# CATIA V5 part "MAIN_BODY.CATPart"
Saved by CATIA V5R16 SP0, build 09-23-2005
Part number: MAIN_BODY
Bounding box of the stored display mesh (mm): x -7.493 to 7.493, y -7.5 to 7.5, z -13 to 86.2
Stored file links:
  D:\Format\Downloads\1_SXEDIA_EKSARTHMATON_POU_DINONTAI_ETOIMA (3) (2)\AMORTISER_parts\MAIN_BODY.CATPart
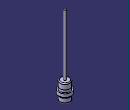
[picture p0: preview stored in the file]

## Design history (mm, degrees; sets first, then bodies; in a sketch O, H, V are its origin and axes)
Body1 (main body)
  Sketch1 on yz-plane, origin (0, 0, 0), H (0, 1, 0), V (0, 0, 1)
    line L1 (0, -13) -> (6, -13)
    line L2 (6, -13) -> (6, -6)
    line L3 (6, -6) -> (6.2, -6)
    line L4 (6.2, -6) -> (6.2, -4)
    line L5 (6.2, -4) -> (7.5, -4)
    line L6 (7.5, -4) -> (7.5, 0)
    point P7 (7.5, 0)
    line L7 (7.5, 0) -> (6, 0)
    line L8 (6, 0) -> (6, 3)
    line L9 (6, 3) -> (6, 3)
    point P10 (6, 3)
    line L10 (6, 3) -> (6, 10)
    line L11 (6, 10) -> (1.5, 10)
    line L12 (1.5, 10) -> (1.5, 86.2)
    line L13 (1.5, 86.2) -> (0, 86.2)
    point P14 (0, 86.2)
    length L13 = 1.5
    length L3 = 0.2
    length L4 = 2
    length L5 = 1.3
    length L6 = 4
    distance V L8 = 6
    length L8 = 3
    distance V L10 = 6
    length L10 = 7
    length L12 = 76.2
    length L1 = 6
    distance H P10 = 3
    length L2 = 7
    horizontal: L1 H, L3 H, L5 H, L7 H, L11 H, L13 H
    vertical: L2 V, L4 V, L6 V, L8 V, L10 V, L12 V
    coincidence: P7 H, P10 L2, P14 V
  Shaft1: profile Sketch1, axis Sketch1.V, angle 360
  Fillet1: radius 2, on edge [face of Shaft1 from Sketch1.L1 | face of Shaft1 from Sketch1.L2]
  Fillet2: radius 1, on edge [face of Shaft1 from Sketch1.L10 | face of Shaft1 from Sketch1.L11]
